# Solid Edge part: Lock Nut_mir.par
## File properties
Author: Sarvanan
Template: Sync Iso Part.par
Last saved by: Sarvanan
Revision: 2
Application: Solid Edge
Username: Sarvanan
Accuracy: 0.990
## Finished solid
Body 1: solid body, 21 faces, 56 edges, 36 vertices.
  Faces by surface: spun 12, plane 8, cylinder 1
  Edges by curve: circle 21, line 18, intersection 17
Bounding box of the edges (mm; curved faces can reach further): 30.022 x 26.000 x 8.000, from (4.7313, -56.9194, 0) to (34.7535, -30.9194, 8).
Cylindrical faces by radius (mm): R6 x1
Planar faces by outward normal: +y 1, +z 1, -y 1, -z 1, oblique 4
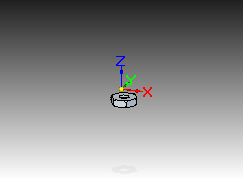
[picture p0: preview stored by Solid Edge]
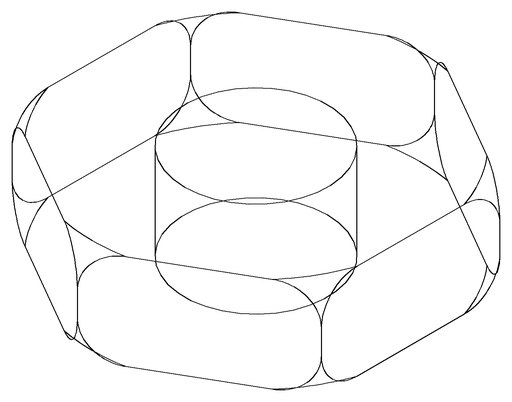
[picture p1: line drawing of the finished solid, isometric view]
